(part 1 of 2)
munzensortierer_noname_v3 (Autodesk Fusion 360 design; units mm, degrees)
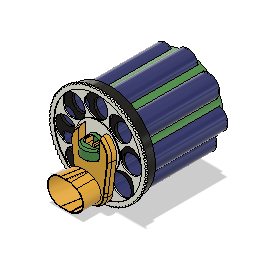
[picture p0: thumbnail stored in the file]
sketch "Skizze1" plane through (0, 0, 0) normal (0, 0, 1) x axis (1, 0, 0)
  line L1 (0, -39.9441) -> (0, 0)
  line L2 (15, 15) -> (-15, 15)
  line L3 (15, -15) -> (15, 15)
  line L4 (-15, -15) -> (15, -15)
  line L5 (-15, 15) -> (-15, -15)
  line L6 (-15, -15) -> (15, 15)
  line L7 (10, -15) -> (15, -10)
  circle C1 centre (0, 0) radius 39.9441
  circle C2 centre (-21.5892, -33.6071) radius 8.5
  circle C3 centre (-37.0016, -15.0471) radius 9.625
  circle C4 centre (-38.4955, 10.6595) radius 10.125
  circle C5 centre (-22.9199, 32.714) radius 10.875
  circle C6 centre (4.4539, 39.695) radius 11.375
  circle C7 centre (30.309, 26.0172) radius 11.875
  circle C8 centre (39.8536, -2.6875) radius 12.375
  circle C9 centre (25.5136, -30.7341) radius 13.125
  circle C10 centre (-21.5892, -33.6071) radius 3
  circle C11 centre (-21.5892, -33.6071) radius 11.5
  circle C12 centre (-37.0016, -15.0471) radius 12.625
  circle C13 centre (-38.4955, 10.6595) radius 13.125
  circle C14 centre (-22.9199, 32.714) radius 13.875
  circle C15 centre (4.4539, 39.695) radius 14.375
  circle C16 centre (30.309, 26.0172) radius 14.875
  circle C17 centre (39.8536, -2.6875) radius 15.375
  circle C18 centre (25.5136, -30.7341) radius 16.125
  circle C19 centre (0, -39.9441) radius 11
  circle C20 centre (0, 0) radius 56.0691
  point P1 (0, 0)
  point P2 (0, 0)
  point P3 (-21.5892, -33.6071)
  point P4 (-37.0016, -15.0471)
  point P5 (-38.4955, 10.6595)
  point P6 (-22.9199, 32.714)
  point P7 (4.4539, 39.695)
  point P8 (30.309, 26.0172)
  point P9 (39.8536, -2.6875)
  point P10 (25.5136, -30.7341)
  point P20 (0, -39.9441)
  point P21 (0, 0)
  point P22 (0, 0)
  point P23 (0, -39.9441)
  point P28 (15, -10)
  point P29 (10, -15)
  point P24 (-15, 15)
  point P25 (15, 15)
  point P27 (-15, -15)
  coincident P1 P2
  coincident C1 P3
  coincident C1 P4
  coincident C1 P5
  coincident C1 P6
  coincident C1 P7
  coincident C1 P8
  coincident C1 P9
  coincident C1 P10
  concentric C2 C10
  concentric C2 C11
  concentric C3 C12
  concentric C4 C13
  concentric C5 C14
  concentric C6 C15
  concentric C7 C16
  concentric C8 C17
  concentric C9 C18
  tangent C11 C12
  tangent C12 C13
  tangent C13 C14
  tangent C14 C15
  tangent C15 C16
  tangent C16 C17
  tangent C17 C18
  coincident C1 P20
  tangent C11 C19
  tangent C18 C19
  coincident P1 P21
  tangent C18 C20
  coincident P1 P22
  coincident P20 P23
  vertical L1
  horizontal L2
  vertical L3
  horizontal L4
  vertical L5
  midpoint P21 L6
  coincident L3 P28
  coincident L4 P29
  dimension "d2" diameter C2 = 17
  dimension "d3" diameter C3 = 19.25 (= "18.75 mm + 0.5 mm")
  dimension "d4" diameter C4 = 20.25 (= "19.75 mm + 0.5 mm")
  dimension "d5" diameter C5 = 21.75
  dimension "d6" diameter C6 = 22.75
  dimension "d7" diameter C7 = 23.75
  dimension "d8" diameter C8 = 24.75
  dimension "d9" diameter C9 = 26.25
  dimension "d10" diameter C10 = 6
  dimension "d11" diameter C11 = 23 (= "d2 + d10")
  dimension "d12" diameter C12 = 25.25 (= "d3 + d10")
  dimension "d13" diameter C13 = 26.25 (= "d4 + d10")
  dimension "d14" diameter C14 = 27.75 (= "d5 + d10")
  dimension "d15" diameter C15 = 28.75 (= "d6 + d10")
  dimension "d16" diameter C16 = 29.75 (= "d7 + d10")
  dimension "d17" diameter C17 = 30.75 (= "d8 + d10")
  dimension "d18" diameter C18 = 32.25 (= "d9 + d10")
  dimension "d19" diameter C19 = 22
  dimension "d21" distance P24 P25 = 30
  dimension "d22" distance P24 P27 = 30
extrude "Extrusion1" new body sketch "Skizze1" profile of C2 C3 C4 C5 C6 C7 C8 C9 C20 L2 L3 L4 L5 L7 along normal blind 3
sketch "Skizze2" plane through (0, 0, 0) normal (0, 0, -1) x axis (-1, 0, 0)
  line L1 (-15, 15) -> (-15, -10)
  line L2 (15, 15) -> (-15, 15)
  line L3 (15, -15) -> (15, 15)
  line L4 (-10, -15) -> (15, -15)
  line L5 (-15, -10) -> (-10, -15)
  circle C1 centre (-4.4539, 39.695) radius 11.375
  circle C2 centre (-30.309, 26.0172) radius 11.875
  circle C3 centre (-39.8536, -2.6875) radius 12.375
  circle C4 centre (-25.5136, -30.7341) radius 13.125
  circle C5 centre (22.9199, 32.714) radius 10.875
  circle C6 centre (21.5892, -33.6071) radius 8.5
  circle C7 centre (37.0016, -15.0471) radius 9.625
  circle C8 centre (38.4955, 10.6595) radius 10.125
  circle C9 centre (0, 0) radius 56.0691
  circle C10 centre (21.5892, -33.6071) radius 9
  circle C11 centre (37.0016, -15.0471) radius 10.125
  circle C12 centre (38.4955, 10.6595) radius 10.625
  circle C13 centre (22.9199, 32.714) radius 11.375
  circle C14 centre (-4.4539, 39.695) radius 11.875
  circle C15 centre (-30.309, 26.0172) radius 12.375
  circle C16 centre (-39.8536, -2.6875) radius 12.875
  circle C17 centre (-25.5136, -30.7341) radius 13.625
  circle C18 centre (-30.309, 26.0172) radius 13.175
  circle C19 centre (-39.8536, -2.6875) radius 13.675
  circle C20 centre (-25.5136, -30.7341) radius 14.425
  circle C21 centre (21.5892, -33.6071) radius 9.8
  circle C22 centre (37.0016, -15.0471) radius 10.925
  circle C23 centre (38.4955, 10.6595) radius 11.425
  circle C24 centre (22.9199, 32.714) radius 12.175
  circle C25 centre (-4.4539, 39.695) radius 12.675
  concentric C6 C10
  concentric C7 C11
  concentric C8 C12
  concentric C5 C13
  concentric C1 C14
  concentric C2 C15
  concentric C3 C16
  concentric C4 C17
  dimension "d25" diameter C10 = 18 (= "d2 + 1 mm")
  dimension "d26" diameter C11 = 20.25 (= "d3 + 1 mm")
  dimension "d27" diameter C12 = 21.25 (= "d4 + 1 mm")
  dimension "d28" diameter C13 = 22.75 (= "d5 + 1 mm")
  dimension "d29" diameter C14 = 23.75 (= "d6 + 1 mm")
  dimension "d30" diameter C15 = 24.75 (= "d7 + 1 mm")
  dimension "d31" diameter C16 = 25.75 (= "d8 + 1 mm")
  dimension "d32" diameter C17 = 27.25 (= "d9 + 1 mm")
  dimension "d33" = 0.8
  dimension "d34" = 0.8
  dimension "d35" = 0.8
  dimension "d36" = 0.8
  dimension "d37" = 0.8
  dimension "d38" = 0.8
  dimension "d39" = 0.8
  dimension "d40" = 0.8
extrude "Extrusion2" new body sketch "Skizze2" profile of C10 C11 C12 C13 C14 C15 C16 C17 C18 C19 C20 C21 C22 C23 C24 C25 along normal blind 100
sketch "Skizze3" plane through (0, 0, -100) normal (0, 0, -1) x axis (-1, 0, 0)
  circle C1 centre (-39.8536, -2.6875) radius 12.875
  circle C2 centre (-39.8536, -2.6875) radius 13.675
  circle C3 centre (21.5892, -33.6071) radius 9
  circle C4 centre (21.5892, -33.6071) radius 9.8
  circle C5 centre (37.0016, -15.0471) radius 10.125
  circle C6 centre (37.0016, -15.0471) radius 10.925
  circle C7 centre (38.4955, 10.6595) radius 10.625
  circle C8 centre (38.4955, 10.6595) radius 11.425
  circle C9 centre (22.9199, 32.714) radius 11.375
  circle C10 centre (22.9199, 32.714) radius 12.175
  circle C11 centre (-4.4539, 39.695) radius 11.875
  circle C12 centre (-4.4539, 39.695) radius 12.675
  circle C13 centre (-30.309, 26.0172) radius 12.375
  circle C14 centre (-30.309, 26.0172) radius 13.175
  circle C15 centre (-39.8536, -2.6875) radius 12.875
  circle C16 centre (-39.8536, -2.6875) radius 13.675
  circle C17 centre (-25.5136, -30.7341) radius 13.625
  circle C18 centre (-25.5136, -30.7341) radius 14.425
extrude "Extrusion3" add sketch "Skizze3" profile of C1 C3 C5 C7 C9 C11 C13 C15 C17 against normal blind 1
sketch "Skizze4" plane through (0, 0, -100) normal (0, 0, -1) x axis (-1, 0, 0)
  circle C1 centre (-30.309, 26.0172) radius 13.175
  circle C2 centre (0, 0) radius 45
  circle C3 centre (-39.8536, -2.6875) radius 13.675
  circle C4 centre (-30.309, 26.0172) radius 13.175
  circle C5 centre (-4.4539, 39.695) radius 12.675
  circle C6 centre (22.9199, 32.714) radius 12.175
  circle C7 centre (38.4955, 10.6595) radius 11.425
  circle C8 centre (37.0016, -15.0471) radius 10.925
  circle C9 centre (21.5892, -33.6071) radius 9.8
  circle C10 centre (-25.5136, -30.7341) radius 14.425
  point P1 (0, 0)
  point P3 (0, 0)
  coincident P1 P3
  dimension "d45" diameter C2 = 90
extrude "Extrusion4" new body sketch "Skizze4" along normal blind 3
extrude "Extrusion5" new body sketch "Skizze4" against normal blind 90
combine "Kombinieren1"
offset_faces "Flächen versetzen1" distance -0.5
sketch "Skizze5" plane through (0, 0, -10) normal (0, 0, 1) x axis (1, 0, 0)
  line L1 (15, 15) -> (-15, 15)
  line L2 (-15, 15) -> (-15, -15)
  line L3 (-15, -15) -> (10, -15)
  line L4 (10, -15) -> (15, -10)
  line L5 (15, -10) -> (15, 15)
  line L6 (14.5, 14.5) -> (-14.5, 14.5)
  line L7 (14.5, -9.7929) -> (14.5, 14.5)
  line L8 (9.7929, -14.5) -> (14.5, -9.7929)
  line L9 (-14.5, -14.5) -> (9.7929, -14.5)
  line L10 (-14.5, 14.5) -> (-14.5, -14.5)
  arc A1 centre (0, 0) radius 45 clockwise from (-31.7457, -31.8938) to (-36.4014, -26.4563)
  arc A2 centre (-21.5892, -33.6071) radius 10.3 clockwise from (-31.7457, -31.8938) to (-15.8083, -42.1319)
  arc A3 centre (0, 0) radius 45 clockwise from (15.8565, -42.1138) to (-15.8083, -42.1319)
  arc A4 centre (25.5136, -30.7341) radius 14.925 clockwise from (15.8565, -42.1138) to (38.4762, -23.3364)
  arc A5 centre (0, 0) radius 45 clockwise from (41.7737, -16.7318) to (38.4762, -23.3364)
  arc A6 centre (39.8536, -2.6875) radius 14.175 clockwise from (41.7737, -16.7318) to (43.6419, 10.9719)
  arc A7 centre (0, 0) radius 45 clockwise from (41.2969, 17.8765) to (43.6419, 10.9719)
  arc A8 centre (30.309, 26.0172) radius 13.675 clockwise from (41.2969, 17.8765) to (23.9269, 38.1117)
  arc A9 centre (0, 0) radius 45 clockwise from (17.5111, 41.4531) to (23.9269, 38.1117)
  arc A10 centre (4.4539, 39.695) radius 13.175 clockwise from (17.5111, 41.4531) to (-7.8889, 44.3031)
  arc A11 centre (0, 0) radius 45 clockwise from (-14.8424, 42.4818) to (-7.8889, 44.3031)
  arc A12 centre (-22.9199, 32.714) radius 12.675 clockwise from (-14.8424, 42.4818) to (-34.859, 28.4579)
  arc A13 centre (0, 0) radius 45 clockwise from (-38.9267, 22.5767) to (-34.859, 28.4579)
  arc A14 centre (-38.4955, 10.6595) radius 11.925 clockwise from (-38.9267, 22.5767) to (-44.9951, 0.6615)
  arc A15 centre (0, 0) radius 45 clockwise from (-44.5343, -6.4571) to (-44.9951, 0.6615)
  arc A16 centre (-37.0016, -15.0471) radius 11.425 clockwise from (-44.5343, -6.4571) to (-36.4014, -26.4563)
  circle C1 centre (-38.4955, 10.6595) radius 10.125
  circle C2 centre (-37.0016, -15.0471) radius 9.625
  circle C3 centre (-21.5892, -33.6071) radius 8.5
  circle C4 centre (-22.9199, 32.714) radius 10.875
  circle C5 centre (25.5136, -30.7341) radius 13.125
  circle C6 centre (39.8536, -2.6875) radius 12.375
  circle C7 centre (30.309, 26.0172) radius 11.875
  circle C8 centre (4.4539, 39.695) radius 11.375
  circle C9 centre (0, 0) radius 56.0691
  dimension "d51" = 0.5
extrude "Extrusion6" add sketch "Skizze5" profile of L6 L10 L9 L7 L8 along normal blind 13
sketch "Skizze6" plane through (0, 0, 0) normal (0, 0, -1) x axis (-1, 0, 0)
  line L1 (-15, 15) -> (-15, -10)
  line L2 (15, 15) -> (-15, 15)
  line L3 (15, -15) -> (15, 15)
  line L4 (-10, -15) -> (15, -15)
  line L5 (-15, -10) -> (-10, -15)
  circle C1 centre (-4.4539, 39.695) radius 11.375
  circle C2 centre (-30.309, 26.0172) radius 11.875
  circle C3 centre (-39.8536, -2.6875) radius 12.375
  circle C4 centre (-25.5136, -30.7341) radius 13.125
  circle C5 centre (22.9199, 32.714) radius 10.875
  circle C6 centre (21.5892, -33.6071) radius 8.5
  circle C7 centre (37.0016, -15.0471) radius 9.625
  circle C8 centre (38.4955, 10.6595) radius 10.125
  circle C9 centre (0, 0) radius 56.0691
  circle C10 centre (-25.5136, -30.7341) radius 14.425
  circle C11 centre (21.5892, -33.6071) radius 9.8
  circle C12 centre (37.0016, -15.0471) radius 10.925
  circle C13 centre (38.4955, 10.6595) radius 11.425
  circle C14 centre (22.9199, 32.714) radius 12.175
  circle C15 centre (-4.4539, 39.695) radius 12.675
  circle C16 centre (-30.309, 26.0172) radius 13.175
  circle C17 centre (-39.8536, -2.6875) radius 13.675
extrude "Extrusion7" new body sketch "Skizze6" profile of L1 L2 L3 L4 L5 C9 C10 C11 C12 C13 C14 C15 C16 C17 along normal blind 9
combine "Kombinieren2"
offset_faces "Flächen versetzen2" distance -0.5
chamfer "Fase1" distance 1
chamfer "Fase2" distance 1.5
chamfer "Fase3" distance 1
sketch "Skizze7" plane through (0, 0, 3) normal (0, 0, 1) x axis (1, 0, 0)
  line L1 (9.7929, -14.5) -> (-14.5, -14.5)
  line L2 (14.5, -9.7929) -> (9.7929, -14.5)
  line L3 (14.5, 14.5) -> (14.5, -9.7929)
  line L4 (-14.5, 14.5) -> (14.5, 14.5)
  line L5 (-14.5, -14.5) -> (-14.5, 14.5)
  circle C1 centre (0, 0) radius 12.5
  point P1 (0, 0)
  point P7 (0, 0)
  coincident P1 P7
  dimension "d60" diameter C1 = 25
extrude "Extrusion8" add sketch "Skizze7" profile of C1 along normal blind 2.6
sketch "Skizze8" plane through (0, 0, 3) normal (0, 0, 1) x axis (1, 0, 0)
  line L1 (9.7929, -14.5) -> (-14.5, -14.5)
  line L2 (14.5, -9.7929) -> (9.7929, -14.5)
  line L3 (14.5, 14.5) -> (14.5, -9.7929)
  line L4 (-14.5, 14.5) -> (14.5, 14.5)
  line L5 (-14.5, -14.5) -> (-14.5, 14.5)
  line L6 (10, -15) -> (-15, -15)
  line L7 (-15, -15) -> (-15, 15)
  line L8 (-15, 15) -> (15, 15)
  line L9 (15, 15) -> (15, -10)
  line L10 (15, -10) -> (10, -15)
  line L11 (29.6375, 10.8589) -> (32.6496, 14.3752)
  line L12 (47.3222, 13.3464) -> (43.4569, 15.8953)
  line L13 (13.2785, 28.6352) -> (12.9219, 33.2516)
  line L14 (24.0246, 42.8991) -> (19.489, 41.9684)
  line L15 (-10.8589, 29.6375) -> (-14.3752, 32.6496)
  line L16 (-13.3464, 47.3222) -> (-15.8953, 43.4569)
  line L17 (-28.6352, 13.2785) -> (-33.2516, 12.9219)
  line L18 (-42.8991, 24.0246) -> (-41.9684, 19.489)
  line L19 (-29.6375, -10.8589) -> (-32.6496, -14.3752)
  line L20 (-47.3222, -13.3464) -> (-43.4569, -15.8953)
  line L21 (-13.2785, -28.6352) -> (-12.9219, -33.2516)
  line L22 (-24.0246, -42.8991) -> (-19.489, -41.9684)
  line L23 (10.8589, -29.6375) -> (14.3752, -32.6496)
  line L24 (13.3464, -47.3222) -> (15.8953, -43.4569)
  line L25 (28.6352, -13.2785) -> (33.2516, -12.9219)
  line L26 (42.8991, -24.0246) -> (41.9684, -19.489)
  circle C1 centre (0, 0) radius 12.5
  circle C2 centre (0, 0) radius 12.75
  circle C3 centre (0, 0) radius 56.0691
  circle C4 centre (4.4539, 39.695) radius 11.375
  circle C5 centre (-22.9199, 32.714) radius 10.875
  circle C6 centre (39.8536, -2.6875) radius 12.375
  circle C7 centre (30.309, 26.0172) radius 11.875
  circle C8 centre (-38.4955, 10.6595) radius 10.125
  circle C9 centre (-37.0016, -15.0471) radius 9.625
  circle C10 centre (-21.5892, -33.6071) radius 8.5
  circle C11 centre (25.5136, -30.7341) radius 13.125
  circle C12 centre (0, 0) radius 57.0691
  circle C13 centre (0, 0) radius 59.0691
  circle C14 centre (-59.069, -0.0741) radius 1.25
  circle C15 centre (-58.8811, -4.7084) radius 1.25
  circle C16 centre (-58.3302, -9.3137) radius 1.25
  circle C17 centre (-57.4197, -13.8615) radius 1.25
  circle C18 centre (-56.1551, -18.3239) radius 1.25
  circle C19 centre (-54.5443, -22.6732) radius 1.25
  circle C20 centre (-52.5972, -26.8829) radius 1.25
  circle C21 centre (-50.3259, -30.9267) radius 1.25
  circle C22 centre (-47.7443, -34.7799) radius 1.25
  circle C23 centre (-44.8683, -38.4187) radius 1.25
  circle C24 centre (-41.7157, -41.8206) radius 1.25
  circle C25 centre (-38.3059, -44.9646) radius 1.25
  circle C26 centre (-34.6599, -47.8314) radius 1.25
  circle C27 centre (-30.8003, -50.4034) radius 1.25
  circle C28 centre (-26.7507, -52.6646) radius 1.25
  circle C29 centre (-22.5362, -54.6011) radius 1.25
  circle C30 centre (-18.1828, -56.2009) radius 1.25
  circle C31 centre (-13.7173, -57.4543) radius 1.25
  circle C32 centre (-9.1672, -58.3534) radius 1.25
  circle C33 centre (-4.5606, -58.8928) radius 1.25
  circle C34 centre (0.0741, -59.069) radius 1.25
  circle C35 centre (4.7084, -58.8811) radius 1.25
  circle C36 centre (9.3137, -58.3302) radius 1.25
  circle C37 centre (13.8615, -57.4197) radius 1.25
  circle C38 centre (18.3239, -56.1551) radius 1.25
  circle C39 centre (22.6732, -54.5443) radius 1.25
  circle C40 centre (26.8829, -52.5972) radius 1.25
  circle C41 centre (30.9267, -50.3259) radius 1.25
  circle C42 centre (34.7799, -47.7443) radius 1.25
  circle C43 centre (38.4187, -44.8683) radius 1.25
  circle C44 centre (41.8206, -41.7157) radius 1.25
  circle C45 centre (44.9646, -38.3059) radius 1.25
  circle C46 centre (47.8314, -34.6599) radius 1.25
  circle C47 centre (50.4034, -30.8003) radius 1.25
  circle C48 centre (52.6646, -26.7507) radius 1.25
  circle C49 centre (54.6011, -22.5362) radius 1.25
  circle C50 centre (56.2009, -18.1828) radius 1.25
  circle C51 centre (57.4543, -13.7173) radius 1.25
  circle C52 centre (58.3534, -9.1672) radius 1.25
  circle C53 centre (58.8928, -4.5606) radius 1.25
  circle C54 centre (59.069, 0.0741) radius 1.25
  circle C55 centre (58.8811, 4.7084) radius 1.25
  circle C56 centre (58.3302, 9.3137) radius 1.25
  circle C57 centre (57.4197, 13.8615) radius 1.25
  circle C58 centre (56.1551, 18.3239) radius 1.25
  circle C59 centre (54.5443, 22.6732) radius 1.25
  circle C60 centre (52.5972, 26.8829) radius 1.25
  circle C61 centre (50.3259, 30.9267) radius 1.25
  circle C62 centre (47.7443, 34.7799) radius 1.25
  circle C63 centre (44.8683, 38.4187) radius 1.25
  circle C64 centre (41.7157, 41.8206) radius 1.25
  circle C65 centre (38.3059, 44.9646) radius 1.25
  circle C66 centre (34.6599, 47.8314) radius 1.25
  circle C67 centre (30.8003, 50.4034) radius 1.25
  circle C68 centre (26.7507, 52.6646) radius 1.25
  circle C69 centre (22.5362, 54.6011) radius 1.25
  circle C70 centre (18.1828, 56.2009) radius 1.25
  circle C71 centre (13.7173, 57.4543) radius 1.25
  circle C72 centre (9.1672, 58.3534) radius 1.25
  circle C73 centre (4.5606, 58.8928) radius 1.25
  circle C74 centre (-0.0741, 59.069) radius 1.25
  circle C75 centre (-4.7084, 58.8811) radius 1.25
  circle C76 centre (-9.3137, 58.3302) radius 1.25
  circle C77 centre (-13.8615, 57.4197) radius 1.25
  circle C78 centre (-18.3239, 56.1551) radius 1.25
  circle C79 centre (-22.6732, 54.5443) radius 1.25
  circle C80 centre (-26.8829, 52.5972) radius 1.25
  circle C81 centre (-30.9267, 50.3259) radius 1.25
  circle C82 centre (-34.7799, 47.7443) radius 1.25
  circle C83 centre (-38.4187, 44.8683) radius 1.25
  circle C84 centre (-41.8206, 41.7157) radius 1.25
  circle C85 centre (-44.9646, 38.3059) radius 1.25
  circle C86 centre (-47.8314, 34.6599) radius 1.25
  circle C87 centre (-50.4034, 30.8003) radius 1.25
  circle C88 centre (-52.6646, 26.7507) radius 1.25
  circle C89 centre (-54.6011, 22.5362) radius 1.25
  circle C90 centre (-56.2009, 18.1828) radius 1.25
  circle C91 centre (-57.4543, 13.7173) radius 1.25
  circle C92 centre (-58.3534, 9.1672) radius 1.25
  circle C93 centre (-58.8928, 4.5606) radius 1.25
  circle C94 centre (0, 0) radius 39.9441
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  point P1 (0, 0)
  point P8 (0, 0)
  point P25 (-59.069, -0.0741)
  point P17 (39.8536, -2.6875)
  point P106 (39.8901, 2.0763)
  point P107 (38.9151, 9.0081)
  point P108 (32.6496, 14.3752)
  coincident P1 P8
  coincident C13 P25
  concentric C3 C94
  coincident P17 C94
  coincident C94 P106
  coincident C94 P107
  coincident C7 P108
  dimension "d63" diameter C2 = 25.5
  dimension "d64" = 1
  dimension "d65" = 3
  dimension "d66" diameter C14 = 2.5
  dimension "d69" diameter = 27
  dimension "d70" diameter = 16.5
  dimension "d71" distance P106 P107 = 7
  dimension "d68" C-Pattern1-Angle = 360
  dimension "d73" C-Pattern2-Angle = 360
extrude "Extrusion9" new body sketch "Skizze8" along normal blind 2.5
chamfer "Fase4" distance 1
sketch "Skizze9" plane through (0, 0, 5.6) normal (0, 0, 1) x axis (1, 0, 0)
  circle C1 centre (0, 0) radius 12.5
sketch "Skizze1" plane through (0, 0, 0) normal (0, 0, 1) x axis (1, 0, 0)
  line L1 (-6, 13) -> (-6, 0)
  line L2 (-6.866, 13.5) -> (-6, 13)
  line L3 (0, 0) -> (-2.7587, 0)
  line L4 (0, -5) -> (0, 0)
  line L5 (-10, -5) -> (0, -5)
  line L6 (-10, 0) -> (-6, 0)
  line L7 (-10, -5) -> (-10, 0)
  line L8 (-6.866, 14.5) -> (-6.866, 13.5)
  line L9 (-5.283, 17.1145) -> (-6.3981, 15.7856)
  line L10 (-4.4, 12.0762) -> (-4.4, 16.7931)
  line L11 (-2.7587, 0) -> (-6, 13)
  line L12 (-4.4, 6.5828) -> (-4.4, 12.0762)
  arc A1 centre (-4.866, 14.5) radius 2 clockwise from (-6.866, 14.5) to (-6.3981, 15.7856)
  arc A2 centre (-4.9, 16.7931) radius 0.5 clockwise from (-5.283, 17.1145) to (-4.4, 16.7931)
  point P1 (0, 0)
  point P6 (0, 0)
  point P13 (-4.4, 12.0762)
  point P14 (-4.4, 6.5828)
  point P2 (-6, 0)
  point P3 (-6, 13)
  point P4 (-6.866, 13.5)
  point P10 (-6.866, 14.5)
  point P7 (0, -5)
  point P8 (-10, -5)
  vertical L1
  coincident P1 P6
  perpendicular L3 L4
  perpendicular L4 L5
  perpendicular L1 L6
  perpendicular L6 L7
  tangent L8 A1
  tangent A1 L9
  horizontal L3
  collinear L3 L6
  vertical L10
  coincident L2 P13
  coincident L11 P14
  parallel L10 L12
  parallel L1 L8
  tangent L9 A2
  tangent L10 A2
  dimension "d1" distance P2 P3 = 13
  dimension "d2_1" distance P3 P4 = 1
  dimension "d8_1" distance P4 P10 = 1
  dimension "d12_1" distance P2 P6 = 6
  dimension "d14_1" angle L1 L11 = 14
  dimension "d18_1" distance L1 L10 = 1.6
  dimension "d19_1" angle L1 L2 = 60
  dimension "d20" radius A2 = 0.5
  dimension "d21_1" angle L9 L10 = 40
  dimension "d22_1" radius A1 = 2
  dimension "d23_1" distance P3 P4 = 0.5
  dimension "d24_1" distance P7 P8 = 10
  dimension "d25_1" distance P6 P7 = 5
extrude "Extrusion1" new body sketch "Skizze1" profile of L1 L2 L3 L4 L5 L6 L7 L8 A1 L9 L10 along normal blind 10 named "d4_1"
fillet "Abrundung1" radius 2 named "d6_1"
sketch "Skizze2" plane through (-15.9382, 12.0815, 0) normal (-0.7969, 0.6041, 0) x axis (0, 0, 1)
  line L1 (0, -0.1023) -> (0, 4.2018)
  line L2 (10, -0.1023) -> (0, -0.1023)
  line L3 (10, 4.2018) -> (10, -0.1023)
  line L4 (0, 4.2018) -> (10, 4.2018)
fillet "Abrundung2" radius 2 named "d15_1"
fillet "Abrundung3" radius 38 named "d16_1"
mirror "Spiegeln"
combine "Kombinieren1"
sketch "Skizze3" plane through (0, 0, 0) normal (0, 1, 0) x axis (-1, 0, 0)
  line L1 (1.1962, 10) -> (1.1962, 0)
  line L2 (-1.1962, 10) -> (1.1962, 10)
  line L3 (-1.1962, 0) -> (-1.1962, 10)
  line L4 (1.1962, 0) -> (-1.1962, 0)
  line L5 (-6, 0) -> (-6, 10)
  line L6 (6, 0) -> (6, 10)
  line L7 (10, 10) -> (10, 0)
  line L8 (-10, 10) -> (-10, 0)
  line L9 (-10, 10) -> (10, 10)
  line L10 (-10, 0) -> (10, 0)
  line L11 (6.2, 10.2) -> (6.2, -0.2)
  line L12 (-6.2, 10.2) -> (6.2, 10.2)
  line L13 (-6.2, 10.2) -> (-6.2, -0.2)
  line L14 (-6.2, -0.2) -> (6.2, -0.2)
  line L15 (6, 10) -> (-6, 0)
  circle C1 centre (0, 5) radius 13
  point P11 (10, 10)
  point P14 (10, 10)
  point P13 (-10, 10)
  point P15 (-10, 10)
  point P10 (10, 0)
  point P16 (10, 0)
  point P12 (-10, 0)
  point P17 (-10, 0)
  point P7 (-6, 0)
  point P23 (-6, 0)
  point P8 (6, 10)
  point P24 (6, 10)
  point P18 (0, 5)
  coincident P11 P14
  coincident P13 P15
  coincident P10 P16
  coincident P12 P17
  coincident P7 P23
  coincident P8 P24
  midpoint P18 L15
  parallel L7 L11
  parallel L9 L12
  parallel L8 L13
  parallel L10 L14
  dimension "d27_1" diameter C1 = 26
  dimension "d29_1" distance L5 L13 = 0.2
  dimension "d30_1" distance L6 L11 = 0.2
  dimension "d31_1" distance L10 L14 = 0.2
  dimension "d32_1" distance L9 L12 = 0.2
extrude "Extrusion2" new body sketch "Skizze3" profile of L7 L8 L9 L10 C1 L11 L12 L13 L14 along normal blind 13.5 named "d33_1"
sketch "Skizze4" plane through (0, 0, -0.2) normal (0, 0, 1) x axis (1, 0, 0)
  line L1 (6.2, 0) -> (-6.2, 0)
  line L2 (6.2, 13.5) -> (6.2, 0)
  line L3 (-6.2, 13.5) -> (6.2, 13.5)
  line L4 (-6.2, 0) -> (-6.2, 13.5)
  line L5 (-3.2712, 2.0555) -> (-3.1368, 1.5162)
  line L6 (-4.4, 16.7931) -> (-4.4, 11.2486)
  line L7 (-6.3981, 15.7856) -> (-5.283, 17.1145)
  line L8 (-6.866, 13.5) -> (-6.866, 14.5)
  line L9 (-6, 13) -> (-6.866, 13.5)
  line L10 (-6, 2) -> (-6, 13)
  line L11 (-10, 0) -> (-8, 0)
  line L12 (-10, -5) -> (-10, 0)
  line L13 (10, -5) -> (-10, -5)
  line L14 (10, 0) -> (10, -5)
  line L15 (8, 0) -> (10, 0)
  line L16 (6, 13) -> (6, 2)
  line L17 (6.866, 13.5) -> (6, 13)
  line L18 (6.866, 14.5) -> (6.866, 13.5)
  line L19 (5.283, 17.1145) -> (6.3981, 15.7856)
  line L20 (4.4, 11.2486) -> (4.4, 16.7931)
  line L21 (3.1368, 1.5162) -> (3.2712, 2.0555)
  line L22 (-1.1962, 0) -> (1.1962, 0)
  line L23 (-13, 13.5) -> (13, 13.5)
  line L24 (-6.666, 13.5) -> (-6.2, 13.2309)
  line L25 (6.666, 13.5) -> (6.2, 13.2309)
  line L26 (8.2, 0) -> (6.2, 2)
  line L27 (-13, 0) -> (13, 0)
  line L28 (-6.2, 2) -> (-8.2, 0)
  arc A1 centre (33.6, 11.2486) radius 38 clockwise from (-3.2712, 2.0555) to (-4.4, 11.2486)
  arc A2 centre (-4.9, 16.7931) radius 0.5 clockwise from (-5.283, 17.1145) to (-4.4, 16.7931)
  arc A3 centre (-4.866, 14.5) radius 2 clockwise from (-6.866, 14.5) to (-6.3981, 15.7856)
  arc A4 centre (-8, 2) radius 2 clockwise from (-6, 2) to (-8, 0)
  arc A5 centre (8, 2) radius 2 clockwise from (8, 0) to (6, 2)
  arc A6 centre (4.866, 14.5) radius 2 clockwise from (6.3981, 15.7856) to (6.866, 14.5)
  arc A7 centre (4.9, 16.7931) radius 0.5 clockwise from (4.4, 16.7931) to (5.283, 17.1145)
  arc A8 centre (-33.6, 11.2486) radius 38 clockwise from (4.4, 11.2486) to (3.2712, 2.0555)
  arc A9 centre (1.1962, 2) radius 2 clockwise from (3.1368, 1.5162) to (1.1962, 0)
  arc A10 centre (-1.1962, 2) radius 2 clockwise from (-1.1962, 0) to (-3.1368, 1.5162)
  point P46 (-6.2, 13.2309)
  point P47 (-6.666, 13.5)
  point P48 (6.2, 13.2309)
  point P49 (6.666, 13.5)
  point P50 (6.2, 2)
  point P51 (8.2, 0)
  point P54 (-8.2, 0)
  point P55 (-6.2, 2)
  point P25 (8, 0)
  point P19 (-8, 0)
  coincident L4 P46
  coincident L23 P47
  parallel L9 L24
  coincident L2 P48
  coincident L23 P49
  parallel L17 L25
  coincident L2 P50
  coincident L15 P51
  coincident L11 P54
  coincident L4 P55
  dimension "d35_1" distance L17 L25 = 0.1
  dimension "d36_1" distance L9 L24 = 0.1
  dimension "d37_1" = 0.1
  dimension "d38_1" angle L26 L27 = 45
  dimension "d39_1" distance P25 P51 = 0.2
  dimension "d40_1" angle L27 L28 = 45
  dimension "d41_1" distance P19 P54 = 0.2
extrude "Extrusion3" cut sketch "Skizze4" profile of L2 L4 A4 L11 L15 A5 L23 L24 L25 L26 L27 L28 along normal blind 10.4 named "d42_1"
extrude "Extrusion4" sketch "Skizze9" along normal blind 39
combine "Kombinieren2"
copy_paste_bodies "Körper ausschneiden/einfügen1"
copy_paste_bodies "Körper ausschneiden/einfügen2"
delete_face "Fläche löschen1"
delete_face "Fläche löschen2"
sketch "Skizze10" plane through (0, 0, 15.6) normal (0, 0, 1) x axis (1, 0, 0)
  line L1 (-3.2712, -4.9445) -> (-3.1368, -5.4838)
  line L2 (-4.4, 9.7931) -> (-4.4, 4.2486)
  line L3 (-6.3981, 8.7856) -> (-5.283, 10.1145)
  line L4 (-6.866, 6.5) -> (-6.866, 7.5)
  line L5 (-6, 6) -> (-6.866, 6.5)
  line L6 (-6, -5) -> (-6, 6)
  line L7 (-10, -7) -> (-8, -7)
  line L8 (-10, -12) -> (-10, -7)
  line L9 (10, -12) -> (-10, -12)
  line L10 (10, -7) -> (10, -12)
  line L11 (8, -7) -> (10, -7)
  line L12 (6, 6) -> (6, -5)
  line L13 (6.866, 6.5) -> (6, 6)
  line L14 (6.866, 7.5) -> (6.866, 6.5)
  line L15 (5.283, 10.1145) -> (6.3981, 8.7856)
  line L16 (4.4, 4.2486) -> (4.4, 9.7931)
  line L17 (3.1368, -5.4838) -> (3.2712, -4.9445)
  line L18 (-1.1962, -7) -> (1.1962, -7)
  line L19 (10, -15) -> (-15, -15)
  line L20 (-15, -15) -> (-15, 15)
  line L21 (-15, 15) -> (15, 15)
  line L22 (15, 15) -> (15, -10)
  line L23 (15, -10) -> (10, -15)
  line L24 (0, -39.9441) -> (0, 0)
  line L25 (12.75, 0) -> (12.75, 19.7405)
  line L26 (-12.75, 0) -> (-12.75, 19.7405)
  line L27 (-18.3545, -42.2598) -> (-23.3152, -2.9416)
  line L28 (18.3545, -42.2598) -> (23.3152, -2.9416)
  line L29 (-11.9249, -33.1746) -> (-12.2814, -28.5582)
  line L30 (-23.8235, -43.8787) -> (-19.288, -42.948)
  line L31 (-33.1746, 11.9249) -> (-28.5582, 12.2814)
  line L32 (-43.8787, 23.8235) -> (-42.948, 19.288)
  line L33 (11.9249, 33.1746) -> (12.2814, 28.5582)
  line L34 (23.8235, 43.8787) -> (19.288, 42.948)
  line L35 (-15.0258, 31.8901) -> (-11.5095, 28.878)
  line L36 (-14.1812, 47.8727) -> (-16.7301, 44.0075)
  line L37 (-31.8901, -15.0258) -> (-28.878, -11.5095)
  line L38 (-47.8727, -14.1812) -> (-44.0075, -16.7301)
  line L39 (31.8901, 15.0258) -> (28.878, 11.5095)
  line L40 (47.8727, 14.1812) -> (44.0075, 16.7301)
  line L41 (33.1746, -11.9249) -> (28.5582, -12.2814)
  line L42 (43.8787, -23.8235) -> (42.948, -19.288)
  line L43 (15.0258, -31.8901) -> (11.5095, -28.878)
  line L44 (14.1812, -47.8727) -> (16.7301, -44.0075)
  arc A1 centre (33.6, 4.2486) radius 38 clockwise from (-3.2712, -4.9445) to (-4.4, 4.2486)
  arc A2 centre (-4.9, 9.7931) radius 0.5 clockwise from (-5.283, 10.1145) to (-4.4, 9.7931)
  arc A3 centre (-4.866, 7.5) radius 2 clockwise from (-6.866, 7.5) to (-6.3981, 8.7856)
  arc A4 centre (-8, -5) radius 2 clockwise from (-6, -5) to (-8, -7)
  arc A5 centre (8, -5) radius 2 clockwise from (8, -7) to (6, -5)
  arc A6 centre (4.866, 7.5) radius 2 clockwise from (6.3981, 8.7856) to (6.866, 7.5)
  arc A7 centre (4.9, 9.7931) radius 0.5 clockwise from (4.4, 9.7931) to (5.283, 10.1145)
  arc A8 centre (-33.6, 4.2486) radius 38 clockwise from (4.4, 4.2486) to (3.2712, -4.9445)
  arc A9 centre (1.1962, -5) radius 2 clockwise from (3.1368, -5.4838) to (1.1962, -7)
  arc A10 centre (-1.1962, -5) radius 2 clockwise from (-1.1962, -7) to (-3.1368, -5.4838)
  circle C1 centre (0, 0) radius 56.0691
  circle C2 centre (4.4539, 39.695) radius 11.375
  circle C3 centre (-22.9199, 32.714) radius 10.875
  circle C4 centre (39.8536, -2.6875) radius 12.375
  circle C5 centre (30.309, 26.0172) radius 11.875
  circle C6 centre (-38.4955, 10.6595) radius 10.125
  circle C7 centre (-37.0016, -15.0471) radius 9.625
  circle C8 centre (-21.5892, -33.6071) radius 8.5
  circle C9 centre (25.5136, -30.7341) radius 13.125
  circle C10 centre (0, 0) radius 39.9441
  circle C11 centre (0, -39.9441) radius 13.5
  circle C12 centre (0, -39.9441) radius 14.1
  circle C13 centre (0, 0) radius 23.5
  arc A11 centre (0, 0) radius 59.0691 clockwise from (-58.9676, -3.4614) to (-59.0542, -1.3241)
  arc A12 centre (-58.8811, -4.7084) radius 1.25 clockwise from (-58.9676, -3.4614) to (-58.7683, -5.9533)
  arc A13 centre (0, 0) radius 59.0691 clockwise from (-58.5142, -8.0773) to (-58.7683, -5.9533)
  arc A14 centre (-58.3302, -9.3137) radius 1.25 clockwise from (-58.5142, -8.0773) to (-58.1201, -10.5459)
  arc A15 centre (0, 0) radius 59.0691 clockwise from (-57.7001, -12.6434) to (-58.1201, -10.5459)
  arc A16 centre (-57.4197, -13.8615) radius 1.25 clockwise from (-57.7001, -12.6434) to (-57.1135, -15.0734)
  arc A17 centre (0, 0) radius 59.0691 clockwise from (-56.5303, -17.1315) to (-57.1135, -15.0734)
  arc A18 centre (-56.1551, -18.3239) radius 1.25 clockwise from (-56.5303, -17.1315) to (-55.7548, -19.508)
  arc A19 centre (0, 0) radius 59.0691 clockwise from (-55.0119, -21.514) to (-55.7548, -19.508)
  arc A20 centre (-54.5443, -22.6732) radius 1.25 clockwise from (-55.0119, -21.514) to (-54.0523, -23.8224)
  arc A21 centre (0, 0) radius 59.0691 clockwise from (-53.1543, -25.7638) to (-54.0523, -23.8224)
  arc A22 centre (-52.5972, -26.8829) radius 1.25 clockwise from (-53.1543, -25.7638) to (-52.0166, -27.9898)
  arc A23 centre (0, 0) radius 59.0691 clockwise from (-50.9691, -29.8549) to (-52.0166, -27.9898)
  arc A24 centre (-50.3259, -30.9267) radius 1.25 clockwise from (-50.9691, -29.8549) to (-49.6602, -31.9847)
  arc A25 centre (0, 0) radius 59.0691 clockwise from (-48.4695, -33.7618) to (-49.6602, -31.9847)
  arc A26 centre (-47.7443, -34.7799) radius 1.25 clockwise from (-48.4695, -33.7618) to (-46.9976, -35.7824)
  arc A27 centre (0, 0) radius 59.0691 clockwise from (-45.6712, -37.4606) to (-46.9976, -35.7824)
  arc A28 centre (-44.8683, -38.4187) radius 1.25 clockwise from (-45.6712, -37.4606) to (-44.0453, -39.3595)
  arc A29 centre (0, 0) radius 59.0691 clockwise from (-42.5913, -40.9285) to (-44.0453, -39.3595)
  arc A30 centre (-41.7157, -41.8206) radius 1.25 clockwise from (-42.5913, -40.9285) to (-40.8214, -42.6939)
  arc A31 centre (0, 0) radius 59.0691 clockwise from (-39.2488, -44.144) to (-40.8214, -42.6939)
  arc A32 centre (-38.3059, -44.9646) radius 1.25 clockwise from (-39.2488, -44.144) to (-37.3458, -45.7651)
  arc A33 centre (0, 0) radius 59.0691 clockwise from (-35.6643, -47.0873) to (-37.3458, -45.7651)
  arc A34 centre (-34.6599, -47.8314) radius 1.25 clockwise from (-35.6643, -47.0873) to (-33.64, -48.5542)
  arc A35 centre (0, 0) radius 59.0691 clockwise from (-31.8599, -49.7403) to (-33.64, -48.5542)
  arc A36 centre (-30.8003, -50.4034) radius 1.25 clockwise from (-31.8599, -49.7403) to (-29.7268, -51.0438)
  arc A37 centre (0, 0) radius 59.0691 clockwise from (-27.8591, -52.0867) to (-29.7268, -51.0438)
  arc A38 centre (-26.7507, -52.6646) radius 1.25 clockwise from (-27.8591, -52.0867) to (-25.6303, -53.2188)
  arc A39 centre (0, 0) radius 59.0691 clockwise from (-23.6866, -54.112) to (-25.6303, -53.2188)
  arc A40 centre (-22.5362, -54.6011) radius 1.25 clockwise from (-23.6866, -54.112) to (-21.3758, -55.0657)
  arc A41 centre (0, 0) radius 59.0691 clockwise from (-19.368, -55.8036) to (-21.3758, -55.0657)
  arc A42 centre (-18.1828, -56.2009) radius 1.25 clockwise from (-19.368, -55.8036) to (-16.9895, -56.5731)
  arc A43 centre (0, 0) radius 59.0691 clockwise from (-14.93, -57.1511) to (-16.9895, -56.5731)
  arc A44 centre (-13.7173, -57.4543) radius 1.25 clockwise from (-14.93, -57.1511) to (-12.4985, -57.7317)
  arc A45 centre (0, 0) radius 59.0691 clockwise from (-10.3999, -58.1464) to (-12.4985, -57.7317)
  arc A46 centre (-9.1672, -58.3534) radius 1.25 clockwise from (-10.3999, -58.1464) to (-7.9304, -58.5343)
  arc A47 centre (0, 0) radius 59.0691 clockwise from (-5.8058, -58.7831) to (-7.9304, -58.5343)
  arc A48 centre (-4.5606, -58.8928) radius 1.25 clockwise from (-5.8058, -58.7831) to (-3.3134, -58.9761)
  arc A49 centre (0, 0) radius 59.0691 clockwise from (-1.1758, -59.0574) to (-3.3134, -58.9761)
  arc A50 centre (0.0741, -59.069) radius 1.25 clockwise from (-1.1758, -59.0574) to (1.3241, -59.0542)
  arc A51 centre (0, 0) radius 59.0691 clockwise from (3.4614, -58.9676) to (1.3241, -59.0542)
  arc A52 centre (4.7084, -58.8811) radius 1.25 clockwise from (3.4614, -58.9676) to (5.9533, -58.7683)
  arc A53 centre (0, 0) radius 59.0691 clockwise from (8.0773, -58.5142) to (5.9533, -58.7683)
  arc A54 centre (9.3137, -58.3302) radius 1.25 clockwise from (8.0773, -58.5142) to (10.5459, -58.1201)
  arc A55 centre (0, 0) radius 59.0691 clockwise from (12.6434, -57.7001) to (10.5459, -58.1201)
  arc A56 centre (13.8615, -57.4197) radius 1.25 clockwise from (12.6434, -57.7001) to (15.0734, -57.1135)
  arc A57 centre (0, 0) radius 59.0691 clockwise from (17.1315, -56.5303) to (15.0734, -57.1135)
  arc A58 centre (18.3239, -56.1551) radius 1.25 clockwise from (17.1315, -56.5303) to (19.508, -55.7548)
  arc A59 centre (0, 0) radius 59.0691 clockwise from (21.514, -55.0119) to (19.508, -55.7548)
  arc A60 centre (22.6732, -54.5443) radius 1.25 clockwise from (21.514, -55.0119) to (23.8224, -54.0523)
  arc A61 centre (0, 0) radius 59.0691 clockwise from (25.7638, -53.1543) to (23.8224, -54.0523)
  arc A62 centre (26.8829, -52.5972) radius 1.25 clockwise from (25.7638, -53.1543) to (27.9898, -52.0166)
  arc A63 centre (0, 0) radius 59.0691 clockwise from (29.8549, -50.9691) to (27.9898, -52.0166)
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  point P52 (-21.5892, -33.6071)
  point P45 (0, 0)
  point P55 (0, 0)
  point P56 (0, -39.9441)
  point P57 (0, -39.9441)
  point P301 (12.75, 19.7405)
  point P303 (-12.75, 19.7405)
  point P306 (-23.3152, -2.9416)
  point P308 (23.3152, -2.9416)
  concentric C1 C10
  coincident P52 C10
  coincident P45 P55
  coincident C10 P56
  perpendicular L9 L24
  coincident P56 P57
  concentric C11 C12
  concentric C10 C13
  coincident C13 P301
  coincident C13 P303
  vertical L26
  vertical L25
  coincident C13 P306
  coincident C13 P308
  tangent C13 L28
  tangent C13 L27
  dimension "d79" diameter C11 = 27
  dimension "d80" diameter C12 = 28.2 (= "27 mm + 1.2 mm")
  dimension "d81" diameter C13 = 47
  dimension "d82" diameter = 37
extrude "Extrusion10" add sketch "Skizze10" against normal blind 10
extrude "Extrusion11" add sketch "Skizze10" profile of C11 C12 along normal blind 10
sketch "Skizze11" plane through (0, 0, 25.6) normal (0, 0, 1) x axis (1, 0, 0)
  circle C1 centre (0, -39.9441) radius 13.5
  circle C2 centre (0, -39.9441) radius 14.1
extrude "Extrusion12" add sketch "Skizze11" along normal blind 20 taper 25
extrude "Extrusion13" cut sketch "Skizze11" profile of C1 along normal blind 20 taper 25
fillet "Abrundung1" radius 3
delete_face "Fläche löschen3"
delete_face "Fläche löschen4"
extrude "Extrusion14" add sketch "Skizze8" profile of C12 C13 C14 C15 C16 C17 C18 C19 C20 C21 C22 C23 C24 C25 C26 C27 C28 C29 C30 C31 C32 C33 C34 C35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 against normal blind 2
sketch "Skizze12" plane through (0, 0, -100) normal (0, 0, -1) x axis (-1, 0, 0)
  curve K1 (23.1281, -37.2992) -> (19.2072, -37.2992)
  curve K2 (23.1281, -27.2992) -> (23.1281, -37.2992)
  curve K3 (19.2072, -27.2992) -> (23.1281, -27.2992)
  curve K4 (19.2072, -37.2992) -> (19.2072, -27.2992)
  curve K5 (39.758, -18.5635) -> (34.6554, -18.5635)
  curve K6 (39.758, -8.5635) -> (39.758, -18.5635)
  curve K7 (34.6554, -8.5635) -> (39.758, -8.5635)
  curve K8 (34.6554, -18.5635) -> (34.6554, -8.5635)
  curve K9 (43.5897, 7.2759) -> (33.5018, 7.2759)
  curve K10 (43.5897, 17.2759) -> (43.5897, 7.2759)
  curve K11 (33.5018, 17.2759) -> (43.5897, 17.2759)
  curve K12 (33.5018, 7.2759) -> (33.5018, 17.2759)
  curve K13 (25.081, 29.0091) -> (19.9394, 29.0091)
  curve K14 (25.081, 39.0091) -> (25.081, 29.0091)
  curve K15 (19.9394, 39.0091) -> (25.081, 39.0091)
  curve K16 (19.9394, 29.0091) -> (19.9394, 39.0091)
  curve K17 (0.5074, 36.2279) -> (-10.1615, 36.2279)
  curve K18 (0.5074, 46.2279) -> (0.5074, 36.2279)
  curve K19 (-10.1615, 46.2279) -> (0.5074, 46.2279)
  curve K20 (-10.1615, 36.2279) -> (-10.1615, 46.2279)
  curve K21 (-21.7528, 22.7437) -> (-37.4022, 22.7437)
  curve K22 (-21.7528, 32.7437) -> (-21.7528, 22.7437)
  curve K23 (-37.4022, 32.7437) -> (-21.7528, 32.7437)
  curve K24 (-37.4022, 22.7437) -> (-37.4022, 32.7437)
  curve K25 (-34.769, -6.362) -> (-45.4086, -6.362)
  curve K26 (-34.769, 3.638) -> (-34.769, -6.362)
  curve K27 (-45.4086, 3.638) -> (-34.769, 3.638)
  curve K28 (-45.4086, -6.362) -> (-45.4086, 3.638)
  curve K29 (-16.8132, -34.8702) -> (-33.0437, -34.8702)
  curve K30 (-16.8132, -24.8702) -> (-16.8132, -34.8702)
  curve K31 (-33.0437, -24.8702) -> (-16.8132, -24.8702)
  curve K32 (-33.0437, -34.8702) -> (-33.0437, -24.8702)
  circle C1 centre (21.5892, -33.6071) radius 9.8
  perpendicular K1 K2
  parallel K1 K3
  parallel K2 K4
  perpendicular K5 K6
  parallel K5 K7
  parallel K6 K8
  perpendicular K9 K10
  parallel K9 K11
  parallel K10 K12
  perpendicular K13 K14
  parallel K13 K15
  parallel K14 K16
  perpendicular K17 K18
  parallel K17 K19
  parallel K18 K20
  perpendicular K21 K22
  parallel K21 K23
  parallel K22 K24
  perpendicular K25 K26
  parallel K25 K27
  parallel K26 K28
  perpendicular K29 K30
  parallel K29 K31
  parallel K30 K32
extrude "Extrusion15" cut sketch "Skizze12" against normal blind 1
copy_paste_bodies "Körper ausschneiden/einfügen1"
copy_paste_bodies "Körper ausschneiden/einfügen2"
copy_paste_bodies "Körper ausschneiden/einfügen3"
copy_paste_bodies "Körper ausschneiden/einfügen4"
copy_paste_bodies "Körper ausschneiden/einfügen5"
copy_paste_bodies "Körper ausschneiden/einfügen6"
copy_paste_bodies "Körper ausschneiden/einfügen7"
move_face "Fläche verschieben1"
sketch "Skizze13" plane through (0, 0, -10) normal (0, 0, 1) x axis (1, 0, 0)
  line L1 (-14.5, 14.5) -> (-14.5, -14.5)
  line L2 (14.5, 14.5) -> (-14.5, 14.5)
  line L3 (14.5, -9.7929) -> (14.5, 14.5)
  line L4 (9.7929, -14.5) -> (14.5, -9.7929)
  line L5 (-14.5, -14.5) -> (9.7929, -14.5)
  arc A1 centre (-22.9199, 32.714) radius 13.675 clockwise from (-13.741, 42.8507) to (-35.5819, 27.5487)
  arc A2 centre (0, 0) radius 45 clockwise from (-38.3252, 23.5834) to (-35.5819, 27.5487)
  arc A3 centre (-38.4955, 10.6595) radius 12.925 clockwise from (-38.3252, 23.5834) to (-44.9971, -0.5112)
  arc A4 centre (0, 0) radius 45 clockwise from (-44.6885, -5.2854) to (-44.9971, -0.5112)
  arc A5 centre (-37.0016, -15.0471) radius 12.425 clockwise from (-44.6885, -5.2854) to (-35.6941, -27.4031)
  arc A6 centre (0, 0) radius 45 clockwise from (-32.5912, -31.0292) to (-35.6941, -27.4031)
  arc A7 centre (-21.5892, -33.6071) radius 11.3 clockwise from (-32.5912, -31.0292) to (-14.6705, -42.5415)
  arc A8 centre (0, 0) radius 45 clockwise from (14.7841, -42.5021) to (-14.6705, -42.5415)
  arc A9 centre (25.5136, -30.7341) radius 15.925 clockwise from (14.7841, -42.5021) to (39.0552, -22.3538)
  arc A10 centre (0, 0) radius 45 clockwise from (41.3342, -17.7901) to (39.0552, -22.3538)
  arc A11 centre (39.8536, -2.6875) radius 15.175 clockwise from (41.3342, -17.7901) to (43.3484, 12.0796)
  arc A12 centre (0, 0) radius 45 clockwise from (41.7403, 16.8151) to (43.3484, 12.0796)
  arc A13 centre (30.309, 26.0172) radius 14.675 clockwise from (41.7403, 16.8151) to (22.945, 38.7108)
  arc A14 centre (0, 0) radius 45 clockwise from (18.5697, 40.9898) to (22.945, 38.7108)
  arc A15 centre (4.4539, 39.695) radius 14.175 clockwise from (18.5697, 40.9898) to (-9.0238, 44.0859)
  arc A16 centre (0, 0) radius 45 clockwise from (-13.741, 42.8507) to (-9.0238, 44.0859)
  arc A17 centre (25.5136, -30.7341) radius 17.525 clockwise from (11.8779, -41.743) to (26.8285, -13.2585)
  arc A18 centre (0, 0) radius 43.4 clockwise from (11.8779, -41.743) to (-11.6344, -41.8115)
  arc A19 centre (-21.5892, -33.6071) radius 12.9 clockwise from (-24.3004, -20.9952) to (-11.6344, -41.8115)
  arc A20 centre (-37.0016, -15.0471) radius 14.025 clockwise from (-31.5788, -2.1129) to (-24.3004, -20.9952)
  arc A21 centre (-38.4955, 10.6595) radius 14.525 clockwise from (-25.7979, 17.7126) to (-31.5788, -2.1129)
  arc A22 centre (-22.9199, 32.714) radius 15.275 clockwise from (-7.9074, 29.8946) to (-25.7979, 17.7126)
  arc A23 centre (4.4539, 39.695) radius 15.775 clockwise from (14.0766, 27.1948) to (-7.9074, 29.8946)
  arc A24 centre (30.309, 26.0172) radius 16.275 clockwise from (28.6794, 9.824) to (14.0766, 27.1948)
  arc A25 centre (39.8536, -2.6875) radius 16.775 clockwise from (26.8285, -13.2585) to (28.6794, 9.824)
  dimension "d29" = 23.75 (= "d6 + 1 mm")
  dimension "d96" = -1.6
extrude "Extrusion16" cut sketch "Skizze13" profile of L1 L2 L3 L4 L5 A24 A17 A18 A19 A20 A21 A22 A23 A25 against normal blind 190 and against normal blind 20
extrude "Extrusion17" cut of existing geometry blind -17 taper -45
move_face "Fläche verschieben2"
chamfer "Fase5" distance 2
sketch "Skizze16" plane through (0, 0, 5.6) normal (0, 0, 1) x axis (1, 0, 0)
  line L1 (-6.666, 6.5) -> (-10.6771, 6.5)
  line L2 (-6.2, 6.2309) -> (-6.666, 6.5)
  line L3 (-6.2, -5) -> (-6.2, 6.2309)
  line L4 (-8.2, -7) -> (-6.2, -5)
  line L5 (-10.3562, -7) -> (-8.2, -7)
  line L6 (8.2, -7) -> (10.3562, -7)
  line L7 (6.2, -5) -> (8.2, -7)
  line L8 (6.2, 6.2309) -> (6.2, -5)
  line L9 (6.666, 6.5) -> (6.2, 6.2309)
  line L10 (10.6771, 6.5) -> (6.666, 6.5)
  arc A1 centre (0, 0) radius 12.5 clockwise from (10.3562, -7) to (-10.3562, -7)
  arc A2 centre (0, 0) radius 12.5 clockwise from (-10.6771, 6.5) to (10.6771, 6.5)
  circle C1 centre (0, 0) radius 12
  point P1 (0, 0)
  point P15 (0, 0)
  coincident P1 P15
  dimension "d111" diameter C1 = 24
extrude "Extrusion20" add sketch "Skizze16" profile of L1 L10 A2 C1 along normal blind 4
fillet "Abrundung2" radius 2
fillet "Abrundung3" radius 2
fillet "Abrundung4" radius 5
extrude "Extrusion21" cut of existing geometry blind -15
